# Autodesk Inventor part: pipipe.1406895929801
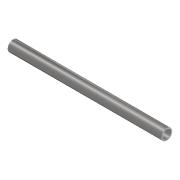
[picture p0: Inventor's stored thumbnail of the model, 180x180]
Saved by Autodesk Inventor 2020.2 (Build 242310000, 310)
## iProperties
Manager: www.cadconsulting.pl
Company: Fabian Stasiak CAD Consulting
IsCustomPart: 1
NAME: PIPING: JIS G 3458 Pipe
DATA: <meta><inlinegroups number="1" deflen="10"></inlinegroups><connections number="2"></connections><angles><a>3.14159265358979</a></angles></meta>
Created: 2014-08
Material: Stal, stopowa
Description: Rura
Document SubType Name: Modeling
Standard: JIS G 3458
Designer: F.Stasiak
Standards Organization: JIS
Language: pl-PL
Size Designation: 40 A x Sch 80 - 100
Categories: <MemberInstance><Categories><Category DisplayName="Rury cienko- i grubościenne" InternalName="4347fa0f-2144-441d-94cd-e3e15c92b736" Mnemonic="TUBEANDPIPE"><Cate
Stock Number: JIS G 3458 Rura 40 A x Sch 80
Density: 7.73 g/cm^3
Appearance: Częściowo polerowana
Catalog Web Link: www.expertbooks.pl
L: 686,000 mm
PL: 686,000 mm
Author: F.Stasiak
Subject: Zbiór ćwiczeń. Autodesk Inventor 2020. Kurs Professional
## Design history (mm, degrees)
sketch "Sketch1"
  geometry: C1 r 24.3 at (0, 0); C2 r 19.2 at (0, 0); 1 further point
  constraints: 2 centre point, 2 coincident, 1 concentric
  dimensions: "d0" = 48.6 diameter of C1 (= OD); "d1" = 38.4 diameter of C2 (= OD - 2 x t)
extrude "Extrusion1" new body sketch "Sketch1" distance "d2" = 686 (= L); taper "d3" = 0 deg
workaxis "Work Axis1"
workpoint "Work Point1"
workaxis "Work Axis2"
workpoint "Work Point2"
body "Solid1"
other parameters: "OD" = 48.6 [user parameter; used in 2 equation terms], "t" = 5.1 [user parameter; used in 1 equation term], "L" = 686 (= PL) [user parameter; used in 1 equation term], "ID" = 38.4 [user parameter], "PL" = 686 [user parameter; used in 1 equation term], "Size_Designation" = 12.345 [user parameter]
